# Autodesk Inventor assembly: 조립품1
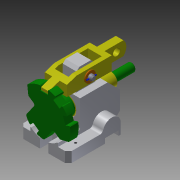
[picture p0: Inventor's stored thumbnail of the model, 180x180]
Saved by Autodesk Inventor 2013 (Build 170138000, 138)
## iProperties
Created: 2016-11
Part Number: 조립품1
Document SubType Name: Assembly
Designer: Administrator
Author: Administrator
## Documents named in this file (8)
- C:\Users\Administrator\Desktop\461108V1037\조립품1.iam
- C:\Users\Administrator\Desktop\461108V1037\본체.ipt
- C:\Users\Administrator\Desktop\461108V1037\부시.ipt
- C:\Users\Administrator\Desktop\461108V1037\분할대.ipt
- C:\Users\Administrator\Desktop\461108V1037\분할축.ipt
- C:\Users\Administrator\Desktop\461108V1037\와셔.ipt
- C:\Users\Administrator\Desktop\461108V1037\원통형핀.ipt
- C:\Users\Administrator\Desktop\461108V1037\클레비스핀.ipt
